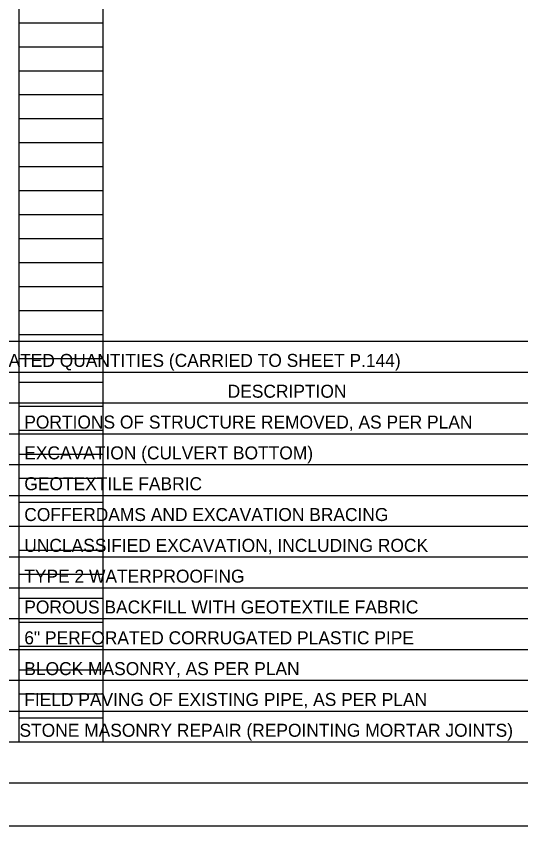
# Model space of a CAD drawing. Extents: x 0 to 34, y 0 to 22.
# Drawn here: x 23.65 to 29.54, y 0 to 9.46 of the extents above; entities that cross this region are included whole.
import ezdxf

# ---------------------------------------------------------------- set-up
doc = ezdxf.new("R2010")
doc.units = 0
for name, color, linetype in [('SH_Border', 7, 'Continuous'), ('SH_Cut_Line', 7, 'Continuous'), ('SH_Data', 7, 'Continuous'), ('SH_Text', 7, 'Continuous')]:
    doc.layers.add(name, color=color, linetype=linetype)

msp = doc.modelspace()

# ---------------------------------------------------------------- linework, layer by layer
at = {"layer": 'SH_Border'}
msp.add_lwpolyline([(1.5, 21.5), (33.5, 21.5), (33.5, 0.5), (1.5, 0.5)], close=True, dxfattribs=at)
at = {"layer": 'SH_Cut_Line'}
msp.add_lwpolyline([(0, 0), (34, 0), (34, 22), (0, 22)], close=True, dxfattribs=at)
at = {"layer": 'SH_Data'}
for p, q in [((23.68, 0.98), (23.68, 21.14)), ((24.66, 0.98), (24.66, 21.14)), ((23.68, 9.38), (24.66, 9.38)), ((23.68, 9.1), (24.66, 9.1)), ((23.68, 8.82), (24.66, 8.82)), ((23.68, 8.54), (24.66, 8.54)), ((23.68, 8.26), (24.66, 8.26)), ((23.68, 7.98), (24.66, 7.98)), ((23.68, 7.7), (24.66, 7.7)), ((23.68, 7.42), (24.66, 7.42)), ((23.68, 7.14), (24.66, 7.14)), ((23.68, 6.86), (24.66, 6.86)), ((23.68, 6.58), (24.66, 6.58)), ((23.68, 6.3), (24.66, 6.3)), ((23.68, 6.02), (24.66, 6.02)), ((23.68, 5.74), (24.66, 5.74)), ((23.68, 5.46), (24.66, 5.46)), ((23.68, 5.18), (24.66, 5.18)), ((23.68, 4.9), (24.66, 4.9)), ((23.68, 4.62), (24.66, 4.62)), ((23.68, 4.34), (24.66, 4.34)), ((23.68, 4.06), (24.66, 4.06)), ((23.68, 3.78), (24.66, 3.78)), ((23.68, 3.5), (24.66, 3.5)), ((23.68, 3.22), (24.66, 3.22)), ((23.68, 2.94), (24.66, 2.94)), ((23.68, 2.66), (24.66, 2.66)), ((23.68, 2.38), (24.66, 2.38)), ((23.68, 2.1), (24.66, 2.1)), ((23.68, 1.82), (24.66, 1.82)), ((23.68, 1.54), (24.66, 1.54)), ((23.68, 1.26), (24.66, 1.26)), ((23.68, 0.98), (24.66, 0.98))]:
    msp.add_line(p, q, dxfattribs=at)
at = {"layer": 'SH_Text'}
for p, q in [((18.968, 5.66), (31.1, 5.66)), ((18.968, 5.3), (31.1, 5.3)), ((18.968, 4.94), (31.1, 4.94)), ((18.968, 4.58), (31.1, 4.58)), ((18.968, 4.22), (31.1, 4.22)), ((18.968, 3.86), (31.1, 3.86)), ((18.968, 3.5), (31.1, 3.5)), ((18.968, 3.14), (31.1, 3.14)), ((18.968, 2.78), (31.1, 2.78)), ((18.968, 2.42), (31.1, 2.42)), ((18.968, 2.06), (31.1, 2.06)), ((18.968, 1.7), (31.1, 1.7)), ((18.968, 1.34), (31.1, 1.34)), ((18.968, 0.98), (31.1, 0.98))]:
    msp.add_line(p, q, dxfattribs=at)

# ---------------------------------------------------------------- texts
for s, p in [('LAK-84-27.10 ESTIMATED QUANTITIES (CARRIED TO SHEET P.144)', (21.627, 5.36)), ('DESCRIPTION', (26.1151, 5)), (' PORTIONS OF STRUCTURE REMOVED, AS PER PLAN', (23.684, 4.64)), (' EXCAVATION (CULVERT BOTTOM)', (23.684, 4.28)), (' GEOTEXTILE FABRIC', (23.684, 3.92)), (' COFFERDAMS AND EXCAVATION BRACING', (23.684, 3.56)), (' UNCLASSIFIED EXCAVATION, INCLUDING ROCK', (23.684, 3.2)), (' TYPE 2 WATERPROOFING', (23.684, 2.84)), (' POROUS BACKFILL WITH GEOTEXTILE FABRIC', (23.684, 2.48)), (' 6" PERFORATED CORRUGATED PLASTIC PIPE', (23.684, 2.12)), (' BLOCK MASONRY, AS PER PLAN', (23.684, 1.76)), (' FIELD PAVING OF EXISTING PIPE, AS PER PLAN', (23.684, 1.4)), ('STONE MASONRY REPAIR (REPOINTING MORTAR JOINTS)', (23.684, 1.04))]:
    msp.add_text(s, height=0.1518, dxfattribs=at).set_placement(p)

doc.saveas('drawing.dxf')
